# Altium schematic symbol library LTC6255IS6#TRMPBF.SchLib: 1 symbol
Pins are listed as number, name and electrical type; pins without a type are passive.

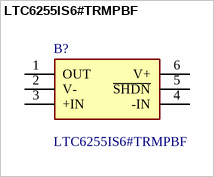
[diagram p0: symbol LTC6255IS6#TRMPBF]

## LTC6255IS6#TRMPBF
designator B?
Precision Amplifiers Single 6.5MHz, 65uA, 1.8V to 5.25V, RRIO Op Amps; Manufacturer_Name: Analog Devices; Geometry.Height: 1mm
footprint SOT95P280X100-6N
pins: 1 OUT, 2 V-, 3 +IN, 4 -IN, 5 ~{SHDN}, 6 V+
